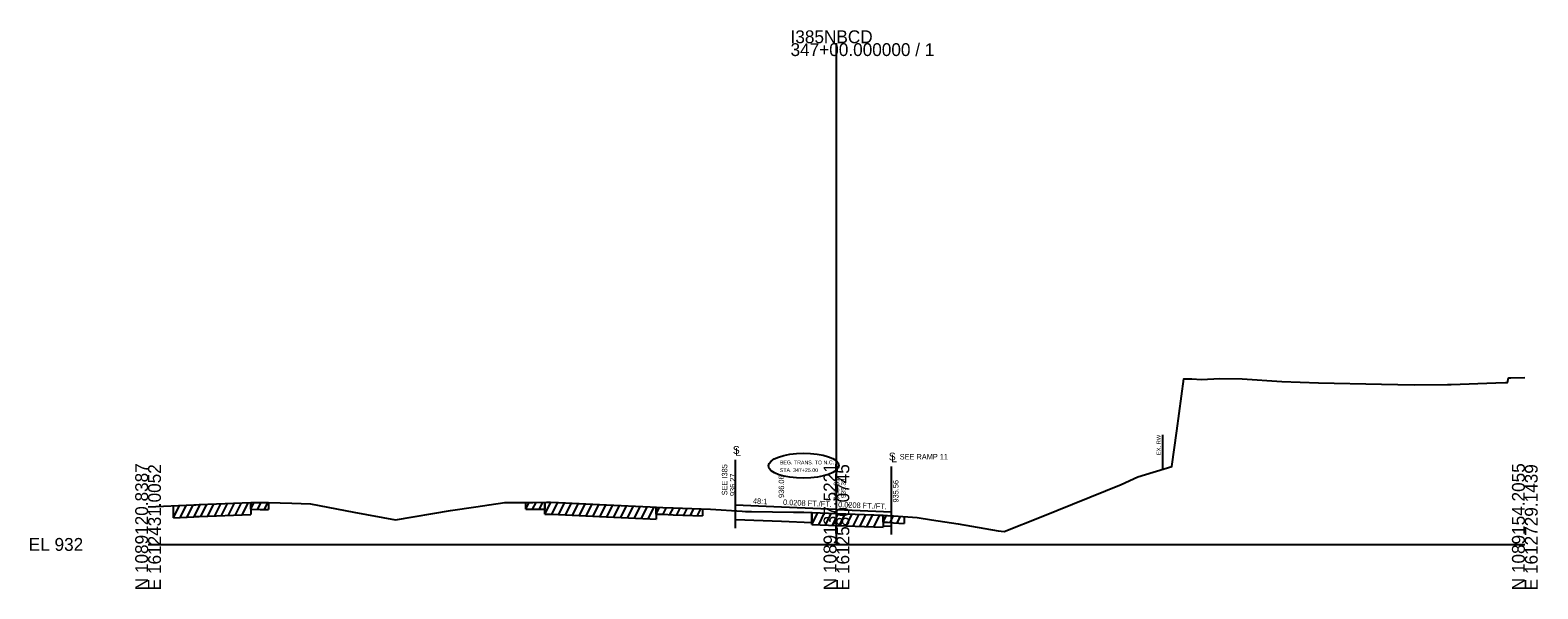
# Model space of a CAD drawing. Extents: x -26 to 1613369, y -10 to 1281970.
# Drawn here: x -25.7 to 302.8, y 16990.3 to 17112.1 of the extents above; entities that cross this region are included whole.
import ezdxf

# ---------------------------------------------------------------- set-up
doc = ezdxf.new("R2010")
doc.units = 0
for name, color, linetype in [('RD_EX_Misc', 7, 'Continuous'), ('RD_GPK_XS_Cell', 7, 'Continuous'), ('RD_Sketch1', 7, 'Continuous'), ('RD_XS_Base', 7, 'Continuous'), ('RD_XS_ExGround', 7, 'Continuous'), ('RD_XS_ExPaveRet', 7, 'Continuous'), ('RD_XS_ExRW', 7, 'Continuous'), ('RD_XS_MatchLine', 7, 'Continuous'), ('RD_XS_Pave', 7, 'Continuous'), ('RD_XS_PaveShd', 7, 'Continuous'), ('RD_XS_TX_Elev_EX', 7, 'Continuous'), ('RD_XS_TX_Elev_PR', 7, 'Continuous'), ('RD_XS_TX_MatchLine', 7, 'Continuous'), ('RD_XS_TX_Notes', 7, 'Continuous'), ('RD_XS_TX_ShdSlope', 7, 'Continuous'), ('RD_XS_TX_Slope', 7, 'Continuous')]:
    doc.layers.add(name, color=color, linetype=linetype)

msp = doc.modelspace()

# ---------------------------------------------------------------- linework, layer by layer
at = {"layer": 'RD_EX_Misc'}
for p, q in [((22.37, 17007.65), (22.37, 17009.15)), ((26.24, 17009.12), (26.24, 17007.62)), ((82.29, 17007.67), (82.29, 17009.17)), ((86.49, 17009.18), (86.49, 17007.68)), ((22.37, 17007.65), (24.46, 17007.64)), ((24.46, 17007.64), (26.24, 17007.62)), ((26.24, 17007.62), (26.24, 17007.62)), ((82.29, 17007.67), (83.81, 17007.67)), ((83.81, 17007.67), (86.49, 17007.68)), ((110.73, 17006.62), (110.73, 17008.12)), ((110.73, 17006.62), (112.18, 17006.56)), ((112.18, 17006.56), (114.39, 17006.47)), ((114.39, 17006.47), (120.79, 17006.23)), ((120.79, 17007.73), (120.79, 17006.23)), ((160.21, 17004.86), (160.21, 17006.36)), ((160.21, 17004.86), (161.1, 17004.83)), ((164.76, 17006.05), (164.76, 17004.55)), ((161.1, 17004.83), (162.47, 17004.72)), ((162.47, 17004.72), (164.76, 17004.55))]:
    msp.add_line(p, q, dxfattribs=at)
at = {"layer": 'RD_GPK_XS_Cell'}
for p, q in [((150, 17000), (150, 17109.27)), ((0, 17000), (150, 17000)), ((150, 17000), (300, 17000))]:
    msp.add_line(p, q, dxfattribs=at)
at = {"layer": 'RD_Sketch1'}
for p, q in [((22.37, 17007.65), (23.12, 17009.14)), ((23.87, 17007.64), (24.62, 17009.14)), ((25.37, 17007.63), (26.12, 17009.13)), ((82.29, 17007.67), (83.04, 17009.17)), ((83.79, 17007.67), (84.54, 17009.17)), ((85.29, 17007.67), (86.04, 17009.18)), ((110.73, 17006.62), (111.46, 17008.09)), ((112.23, 17006.56), (112.96, 17008.03)), ((113.73, 17006.5), (114.46, 17007.97)), ((115.23, 17006.44), (115.96, 17007.91)), ((116.73, 17006.38), (117.46, 17007.85)), ((118.23, 17006.32), (118.96, 17007.8)), ((119.73, 17006.27), (120.46, 17007.74)), ((160.21, 17004.86), (160.94, 17006.33)), ((161.71, 17004.78), (162.43, 17006.22)), ((163.21, 17004.67), (163.93, 17006.11))]:
    msp.add_line(p, q, dxfattribs=at)
at = {"layer": 'RD_XS_Base'}
for p, q in [((128, 17005.38), (128, 17007.33)), ((138, 17004.96), (128, 17005.38)), ((144.64, 17004.68), (138, 17004.96)), ((144.64, 17006.96), (144.74, 17006.96)), ((144.64, 17006.96), (144.64, 17004.68)), ((144.74, 17006.96), (150, 17006.75)), ((150, 17006.75), (156.13, 17006.51)), ((156.13, 17006.51), (160.21, 17006.36)), ((160.21, 17006.36), (160.21, 17004.04)), ((162, 17003.96), (162, 17006.26)), ((160.21, 17004.04), (162, 17003.96))]:
    msp.add_line(p, q, dxfattribs=at)
at = {"layer": 'RD_XS_ExGround'}
msp.add_lwpolyline([(0, 17008.16), (10, 17008.63), (10.4, 17008.65), (11.14, 17008.68), (22.37, 17009.15), (24.46, 17009.14), (26.24, 17009.12), (31.34, 17009.02), (35.43, 17008.87), (44.85, 17007.03), (53.89, 17005.37), (65.9, 17007.38), (71.45, 17008.17), (74.35, 17008.66), (77.74, 17009.17), (81.32, 17009.16), (83.81, 17009.17), (86.81, 17009.18), (87.7, 17009.18), (89.43, 17009.1), (99.88, 17008.62), (109.38, 17008.19), (112.18, 17008.06), (114.39, 17007.97), (122.55, 17007.66), (129.45, 17007.25), (130.2, 17007.2), (131.47, 17007.18), (140.63, 17007.05), (142.87, 17007), (144.74, 17006.96), (150, 17006.75), (156.13, 17006.51), (161.1, 17006.33), (162.47, 17006.22), (167.59, 17005.84), (170.73, 17005.37), (176.5, 17004.5), (185.26, 17002.99), (186.57, 17002.79), (194.64, 17005.99), (212.01, 17013.03), (215.7, 17014.71), (223.12, 17017.01), (224.18, 17024.79), (225.73, 17036.1), (227.43, 17036.1), (229.57, 17035.98), (233.53, 17036.14), (238.39, 17036.08), (247.04, 17035.49), (255.06, 17035.25), (268.78, 17034.9), (275.88, 17034.79), (283.12, 17034.89), (283.95, 17034.88), (293.68, 17035.21), (295.78, 17035.28), (296.22, 17035.3), (296.48, 17036.3), (296.98, 17036.3), (300, 17036.42)], dxfattribs=at)
at = {"layer": 'RD_XS_ExPaveRet'}
for p, q in [((5.52, 17005.82), (6.85, 17008.48)), ((5.52, 17005.82), (5.52, 17008.42)), ((7.02, 17005.89), (8.35, 17008.56)), ((8.52, 17005.96), (9.85, 17008.63)), ((10.02, 17006.03), (11.35, 17008.69)), ((11.52, 17006.1), (12.84, 17008.75)), ((13.02, 17006.16), (14.34, 17008.82)), ((14.52, 17006.22), (15.84, 17008.88)), ((16.02, 17006.29), (17.34, 17008.94)), ((17.52, 17006.35), (18.85, 17009)), ((19.02, 17006.41), (20.35, 17009.06)), ((20.52, 17006.47), (21.85, 17009.13)), ((22.37, 17009.15), (22.37, 17006.55)), ((86.49, 17006.58), (86.49, 17009.18)), ((86.49, 17006.58), (87.79, 17009.17)), ((87.99, 17006.56), (89.26, 17009.1)), ((89.49, 17006.49), (90.76, 17009.04)), ((90.99, 17006.43), (92.26, 17008.97)), ((92.49, 17006.36), (93.76, 17008.9)), ((93.99, 17006.29), (95.26, 17008.83)), ((95.49, 17006.22), (96.76, 17008.76)), ((96.99, 17006.15), (98.26, 17008.69)), ((98.49, 17006.08), (99.76, 17008.62)), ((99.99, 17006.01), (101.26, 17008.56)), ((101.49, 17005.95), (102.76, 17008.49)), ((102.99, 17005.88), (104.26, 17008.42)), ((104.49, 17005.81), (105.76, 17008.35)), ((105.99, 17005.74), (107.26, 17008.28)), ((107.49, 17005.67), (108.76, 17008.21)), ((108.99, 17005.6), (110.26, 17008.15)), ((5.52, 17005.82), (10, 17006.03)), ((10, 17006.03), (10.4, 17006.05)), ((10.4, 17006.05), (11.14, 17006.08)), ((11.14, 17006.08), (22.37, 17006.55)), ((86.49, 17006.58), (86.81, 17006.58)), ((86.81, 17006.58), (87.7, 17006.58)), ((87.7, 17006.58), (89.43, 17006.5)), ((89.43, 17006.5), (99.88, 17006.02)), ((99.88, 17006.02), (109.38, 17005.59)), ((109.38, 17005.59), (110.73, 17005.52)), ((110.73, 17008.12), (110.73, 17005.52)), ((144.64, 17004.36), (144.64, 17006.96)), ((144.64, 17004.36), (145.92, 17006.91)), ((146.14, 17004.3), (147.42, 17006.85)), ((147.64, 17004.24), (148.92, 17006.79)), ((149.14, 17004.19), (150.42, 17006.74)), ((150.64, 17004.13), (151.92, 17006.68)), ((152.14, 17004.07), (153.42, 17006.62)), ((153.64, 17004.01), (154.92, 17006.56)), ((155.14, 17003.95), (156.42, 17006.5)), ((156.64, 17003.89), (157.92, 17006.45)), ((158.14, 17003.84), (159.42, 17006.39)), ((160.21, 17006.36), (160.21, 17003.76)), ((144.64, 17004.36), (144.74, 17004.36)), ((144.74, 17004.36), (150, 17004.15)), ((150, 17004.15), (156.13, 17003.91)), ((156.13, 17003.91), (160.21, 17003.76))]:
    msp.add_line(p, q, dxfattribs=at)
at = {"layer": 'RD_XS_ExRW'}
msp.add_line((221.02, 17023.88), (221.02, 17016.36), dxfattribs=at)
at = {"layer": 'RD_XS_MatchLine'}
for p, q in [((128, 17007.33), (128, 17008.54)), ((162, 17006.26), (162, 17007.13)), ((162, 17006.26), (162, 17007.13))]:
    msp.add_line(p, q, dxfattribs=at)
at = {"layer": 'RD_XS_Pave'}
for q in [(138, 17008.13), (162, 17007.13)]:
    msp.add_line((150, 17007.63), q, dxfattribs=at)
at = {"layer": 'RD_XS_PaveShd'}
msp.add_line((138, 17008.13), (128, 17008.54), dxfattribs=at)
at = {"layer": 'RD_XS_TX_MatchLine'}
for p, q in [((128, 17008.54), (128, 17018.43)), ((162, 17007.13), (162, 17017.01)), ((128, 17003.54), (128, 17008.54)), ((162, 17002.13), (162, 17007.13))]:
    msp.add_line(p, q, dxfattribs=at)
at = {"layer": 'RD_XS_TX_Notes'}
msp.add_ellipse((142.84, 17017.16), major_axis=(7.68, 0.05), ratio=0.355189, dxfattribs=at)

# ---------------------------------------------------------------- texts
at = {"layer": 'RD_GPK_XS_Cell'}
for s, p in [('I385NBCD', (140, 17109.27)), ('347+00.000000 / 1', (140, 17106.47)), ('EL 932', (-26, 16998.6))]:
    msp.add_text(s, height=2.8, dxfattribs=at).set_placement(p)
for s, p in [('N 1089120.8387', (0, 16990)), ('E 1612431.0052', (2.8, 16990)), ('N 1089137.5221', (150, 16990)), ('E 1612580.0745', (152.8, 16990)), ('N 1089154.2055', (300, 16990)), ('E 1612729.1439', (302.8, 16990))]:
    msp.add_text(s, height=2.8, rotation=90, dxfattribs=at).set_placement(p)
at = {"layer": 'RD_XS_ExRW'}
msp.add_text('EX. RW', height=0.9, rotation=90, dxfattribs=at).set_placement((220.66, 17019.47))
at = {"layer": 'RD_XS_TX_Elev_EX'}
msp.add_text('935.38', height=1, rotation=90, dxfattribs=at).set_placement((152, 17010.13))
at = {"layer": 'RD_XS_TX_Elev_PR'}
for s, p in [('936.27', (128, 17010.54)), ('936.06', (138.6, 17010.13)), ('935.81', (150.6, 17009.63)), ('935.56', (163.52, 17009.13))]:
    msp.add_text(s, height=1.2, rotation=90, dxfattribs=at).set_placement(p)
at = {"layer": 'RD_XS_TX_MatchLine'}
for s, p in [('S', (127.42, 17019.75)), ('L', (127.93, 17019.31)), ('S', (161.42, 17018.33)), ('L', (161.93, 17017.89))]:
    msp.add_text(s, height=1.68, dxfattribs=at).set_placement(p)
at = {"layer": 'RD_XS_TX_Notes'}
for s, height, p in [('BEG. TRANS. TO N.C.', 0.8333, (137.66, 17017.45)), ('SEE RAMP 11', 1.2, (163.78, 17018.52)), ('STA. 347+25.00', 0.8333, (137.66, 17015.78))]:
    msp.add_text(s, height=height, dxfattribs=at).set_placement(p)
msp.add_text('SEE I385', height=1.2, rotation=90, dxfattribs=at).set_placement((126.23, 17010.71))
at = {"layer": 'RD_XS_TX_ShdSlope'}
msp.add_text('48:1', height=1.2, rotation=357.6141, dxfattribs=at).set_placement((131.79, 17008.88))
at = {"layer": 'RD_XS_TX_Slope'}
for p in [(138.35, 17008.61), (150.35, 17008.11)]:
    msp.add_text('0.0208 FT./FT.', height=1.2, rotation=357.6141, dxfattribs=at).set_placement(p)

doc.saveas('drawing.dxf')
